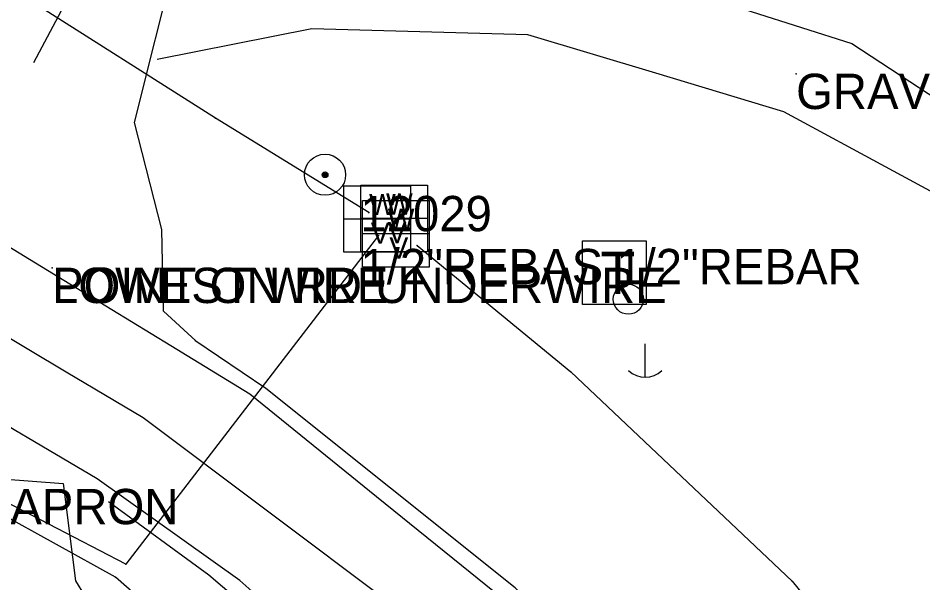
# Model space of a CAD drawing. Extents: x 1050807 to 1053552, y 395828 to 398415.
# Drawn here: x 1051909.5 to 1052037.5, y 397988.8 to 398068.8 of the extents above; entities that cross this region are included whole.
import ezdxf

# ---------------------------------------------------------------- set-up
doc = ezdxf.new("R2010")
doc.units = 0
for name, color, linetype in [('S_EDGE_PAVEMENT', 7, 'Continuous'), ('S_ELECTRIC_UTILITIES_ANNOT', 7, 'Continuous'), ('S_GRAVEL_ROAD', 7, 'Continuous'), ('S_IRON_PIN', 7, 'Continuous'), ('S_IRON_PIN_ANNOT', 7, 'Continuous'), ('S_MSC_PT_SYM', 7, 'Continuous'), ('S_PAVEMENT_CROWN', 7, 'Continuous'), ('S_SHOULDER', 7, 'Continuous'), ('S_SURVEY_TEXT_ANNOT', 7, 'Continuous'), ('S_TELEPHONE_UTILITIES', 7, 'Continuous'), ('S_UTILITY_POLE', 7, 'Continuous'), ('S_UTL_PT_SYM', 7, 'Continuous'), ('S_WATER_UTILITIES', 7, 'Continuous')]:
    doc.layers.add(name, color=color, linetype=linetype)

msp = doc.modelspace()

# ---------------------------------------------------------------- linework, layer by layer
at = {"layer": 'S_EDGE_PAVEMENT'}
for points in [[(1051934.63, 398023.1), (1051930.06, 398027.26), (1051929.8, 398038.82), (1051925.96, 398053.99), (1051931.83, 398077.54), (1051938.69, 398100.99), (1051941.54, 398122.27), (1051942, 398134.91), (1051942.46, 398147.55), (1051942.93, 398160.19), (1051943.39, 398172.83), (1051943.59, 398197.73), (1051943.79, 398222.64), (1051944.04, 398235.63), (1051944.3, 398248.63), (1051944.55, 398261.62), (1051944.81, 398274.62), (1051944.95, 398287.8), (1051945.09, 398300.98), (1051945.24, 398314.17), (1051945.38, 398327.35), (1051945.7, 398344.1), (1051946.02, 398360.85)], [(1052043.7, 397907.48), (1052036.23, 397917.81), (1052028.77, 397928.15), (1052021.31, 397938.48), (1052013.84, 397948.81), (1052004.91, 397958.24), (1051995.98, 397967.66), (1051987.04, 397977.09), (1051978.11, 397986.52), (1051960.19, 398001.02), (1051942.28, 398015.53), (1051931.11, 398022.36), (1051919.95, 398029.19), (1051908.79, 398036.02), (1051897.62, 398042.85), (1051877.43, 398052.09), (1051857.24, 398061.33), (1051844.58, 398065.54), (1051831.93, 398069.76)], [(1052038.69, 397873.19), (1052032.04, 397883.85), (1052025.39, 397894.51), (1052018.74, 397905.17), (1052012.09, 397915.83), (1052004.02, 397925.46), (1051995.95, 397935.08), (1051987.88, 397944.7), (1051979.81, 397954.32), (1051970.07, 397963.03), (1051960.33, 397971.74), (1051950.59, 397980.46), (1051940.85, 397989.17), (1051920.67, 398003.53), (1051900.02, 398015.7), (1051879.38, 398027.86), (1051867.4, 398032.67), (1051855.43, 398037.49), (1051843.45, 398042.3), (1051831.48, 398047.11), (1051807.63, 398052.86)]]:
    msp.add_lwpolyline(points, dxfattribs=at)
at = {"layer": 'S_GRAVEL_ROAD'}
for points in [[(1051941.6, 398111.76), (1051957.6, 398097.06), (1051970.21, 398085.36), (1051984.67, 398078.88), (1052006.03, 398072.02), (1052027.38, 398065.17), (1052046.41, 398052.69), (1052065.44, 398040.21), (1052080.08, 398025.28), (1052094.72, 398010.35), (1052105.27, 397991.93), (1052108.07, 397979.7), (1052110.87, 397967.48), (1052113.67, 397955.25), (1052116.48, 397943.02), (1052122.03, 397920.87), (1052127.57, 397898.72), (1052130.86, 397881.88), (1052134.15, 397865.05), (1052139.91, 397846.05), (1052147.47, 397834.83)], [(1052123.52, 397838.53), (1052126.37, 397842.85), (1052127.19, 397846.52), (1052118.6, 397865.94), (1052112.52, 397878.14), (1052106.44, 397890.34), (1052105.1, 397906.73), (1052103.75, 397923.13), (1052099.75, 397943.42), (1052095.74, 397963.72), (1052086.81, 397984.21), (1052077.87, 398004.7), (1052063.35, 398021.7), (1052048.82, 398038.69), (1052033.31, 398047.09), (1052017.79, 398055.49), (1051999.69, 398060.95), (1051981.6, 398066.41), (1051966.31, 398066.83), (1051951.02, 398067.25), (1051929.14, 398062.88)], [(1051907.2, 398003.55), (1051915.88, 398002.91), (1051917.6, 397989.1), (1051925.25, 397976.64), (1051940.24, 397961.7), (1051955.22, 397946.76), (1051966.38, 397933.09), (1051977.54, 397919.42), (1051982.83, 397903.76), (1051988.12, 397888.11), (1051995.11, 397874.29), (1052002.09, 397860.47), (1052012.08, 397846.73), (1052024.66, 397838)]]:
    msp.add_lwpolyline(points, dxfattribs=at)
at = {"layer": 'S_IRON_PIN'}
for radius in [2.91, 0.411, 0.262, 0.212, 0.145, 0.0822, 0.0581]:
    msp.add_circle((1051952.9, 398046.59), radius, dxfattribs=at)
at = {"layer": 'S_MSC_PT_SYM'}
for points in [[(1052019.52, 398060.89), (1052019.52, 398060.94), (1052019.52, 398060.89), (1052019.47, 398060.89), (1052019.52, 398060.89), (1052019.52, 398060.84), (1052019.52, 398060.89), (1052019.57, 398060.89)], [(1051914.29, 398033.43), (1051914.29, 398033.48), (1051914.29, 398033.43), (1051914.24, 398033.43), (1051914.29, 398033.43), (1051914.29, 398033.38), (1051914.29, 398033.43), (1051914.34, 398033.43)]]:
    msp.add_lwpolyline(points, dxfattribs=at)
at = {"layer": 'S_PAVEMENT_CROWN'}
for points in [[(1051911.73, 398062.49), (1051922.6, 398083.01), (1051926.16, 398095.8), (1051929.71, 398108.59), (1051932.19, 398128.36), (1051932.65, 398140.95), (1051933.12, 398153.54), (1051933.58, 398166.13), (1051934.04, 398178.71), (1051934.3, 398191.33), (1051934.55, 398203.94), (1051934.81, 398216.55), (1051935.06, 398229.16), (1051935.51, 398253.78), (1051935.96, 398278.4), (1051936.1, 398291.5), (1051936.24, 398304.61), (1051936.39, 398317.72), (1051936.53, 398330.82), (1051937.06, 398346.12), (1051937.6, 398361.41)], [(1052041.36, 397889.37), (1052035.08, 397900.29), (1052028.8, 397911.2), (1052020.99, 397921.23), (1052013.18, 397931.25), (1052005.37, 397941.28), (1051997.56, 397951.3), (1051979.95, 397968.52), (1051962.34, 397985.74), (1051944.75, 397998.96), (1051927.16, 398012.19), (1051916.3, 398018.66), (1051905.43, 398025.13), (1051894.57, 398031.6), (1051883.71, 398038.07), (1051871.84, 398042.85), (1051859.97, 398047.63), (1051848.1, 398052.42), (1051836.23, 398057.2), (1051823.74, 398060.25), (1051811.24, 398063.31)]]:
    msp.add_lwpolyline(points, dxfattribs=at)
at = {"layer": 'S_SHOULDER'}
for points in [[(1052069.97, 397864.61), (1052063.87, 397875.65), (1052057.77, 397886.69), (1052051.67, 397897.73), (1052045.57, 397908.78), (1052038.12, 397919.18), (1052030.67, 397929.57), (1052023.22, 397939.97), (1052015.78, 397950.37), (1052006.78, 397959.81), (1051997.77, 397969.24), (1051988.77, 397978.67), (1051979.77, 397988.1), (1051962.15, 398002.23), (1051944.53, 398016.35), (1051934.5, 398023.11)], [(1052050.55, 397842.58), (1052039.7, 397864.61), (1052028.85, 397886.64), (1052021.35, 397897.42), (1052013.86, 397908.2), (1052006.37, 397918.98), (1051998.87, 397929.76), (1051981.88, 397947.71), (1051964.88, 397965.66), (1051950.67, 397977.79), (1051936.46, 397989.93), (1051922.29, 398000.29)]]:
    msp.add_lwpolyline(points, dxfattribs=at)
at = {"layer": 'S_TELEPHONE_UTILITIES'}
msp.add_lwpolyline([(1051989.3, 398028.22), (1051989.3, 398037.22), (1051998.3, 398037.22), (1051998.3, 398028.22)], close=True, dxfattribs=at)
at = {"layer": 'S_UTILITY_POLE'}
for p, q in [((1051995.68, 398031.11), (1051995.68, 398033.22)), ((1051998.12, 398022.64), (1051998.12, 398017.91))]:
    msp.add_line(p, q, dxfattribs=at)
msp.add_circle((1051995.8, 398028.97), 2.13, dxfattribs=at)
msp.add_arc((1051998.18, 398021.33), 3.41, 226.3972, 313.6028, dxfattribs=at)
at = {"layer": 'S_UTL_PT_SYM'}
for points in [[(1051937.42, 398054.58), (1051937.42, 398054.63), (1051937.42, 398054.58), (1051937.37, 398054.58), (1051937.42, 398054.58), (1051937.42, 398054.53), (1051937.42, 398054.58), (1051937.47, 398054.58)], [(1051959.07, 398041.23), (1051959.07, 398041.28), (1051959.07, 398041.23), (1051959.02, 398041.23), (1051959.07, 398041.23), (1051959.07, 398041.18), (1051959.07, 398041.23), (1051959.12, 398041.23)], [(1051960.46, 398037.97), (1051960.46, 398038.02), (1051960.46, 398037.97), (1051960.41, 398037.97), (1051960.46, 398037.97), (1051960.46, 398037.92), (1051960.46, 398037.97), (1051960.51, 398037.97)], [(1051965.92, 398036.58), (1051965.92, 398036.63), (1051965.92, 398036.58), (1051965.87, 398036.58), (1051965.92, 398036.58), (1051965.92, 398036.53), (1051965.92, 398036.58), (1051965.97, 398036.58)], [(1051914.29, 398033.43), (1051914.29, 398033.48), (1051914.29, 398033.43), (1051914.24, 398033.43), (1051914.29, 398033.43), (1051914.29, 398033.38), (1051914.29, 398033.43), (1051914.34, 398033.43)], [(1051987.66, 398018.71), (1051987.66, 398018.76), (1051987.66, 398018.71), (1051987.61, 398018.71), (1051987.66, 398018.71), (1051987.66, 398018.66), (1051987.66, 398018.71), (1051987.71, 398018.71)], [(1051924.71, 397991.46), (1051924.71, 397991.51), (1051924.71, 397991.46), (1051924.66, 397991.46), (1051924.71, 397991.46), (1051924.71, 397991.41), (1051924.71, 397991.46), (1051924.76, 397991.46)], [(1051923.28, 397989.65), (1051923.28, 397989.7), (1051923.28, 397989.65), (1051923.23, 397989.65), (1051923.28, 397989.65), (1051923.28, 397989.6), (1051923.28, 397989.65), (1051923.33, 397989.65)], [(1052018.98, 397989.06), (1052018.98, 397989.11), (1052018.98, 397989.06), (1052018.93, 397989.06), (1052018.98, 397989.06), (1052018.98, 397989.01), (1052018.98, 397989.06), (1052019.03, 397989.06)]]:
    msp.add_lwpolyline(points, dxfattribs=at)
at = {"layer": 'S_WATER_UTILITIES'}
for p, q in [((1051937.42, 398054.58), (1051898.42, 398079.37)), ((1051959.07, 398041.23), (1051937.42, 398054.58)), ((1051955.57, 398045.03), (1051964.99, 398045.03)), ((1051955.57, 398035.61), (1051955.57, 398045.03)), ((1051957.96, 398045.12), (1051967.38, 398045.12)), ((1051957.96, 398035.7), (1051957.96, 398045.12)), ((1051964.99, 398045.03), (1051964.99, 398035.61)), ((1051967.38, 398045.12), (1051967.38, 398035.7)), ((1051958.21, 398042.94), (1051967.63, 398042.94)), ((1051958.21, 398033.53), (1051958.21, 398042.94)), ((1051967.63, 398042.94), (1051967.63, 398033.53)), ((1051955.57, 398040.34), (1051964.99, 398040.34)), ((1051957.96, 398040.43), (1051967.38, 398040.43)), ((1051958.21, 398038.25), (1051967.63, 398038.25)), ((1051960.46, 398037.97), (1051924.71, 397991.46)), ((1051964.99, 398035.61), (1051955.57, 398035.61)), ((1051967.38, 398035.7), (1051957.96, 398035.7)), ((1051965.92, 398036.58), (1051987.66, 398018.71)), ((1051967.63, 398033.53), (1051958.21, 398033.53)), ((1051924.71, 397991.46), (1051862.03, 398024.03)), ((1051923.28, 397989.65), (1051871.96, 398018.02)), ((1051987.66, 398018.71), (1052018.98, 397989.06)), ((1051964.28, 397953.57), (1051923.28, 397989.65)), ((1052018.98, 397989.06), (1052053.44, 397946.43))]:
    msp.add_line(p, q, dxfattribs=at)

# ---------------------------------------------------------------- texts
at = {"layer": 'S_ELECTRIC_UTILITIES_ANNOT'}
msp.add_text('LOWEST WIRE', height=5, dxfattribs=at).set_placement((1051914.29, 398028.43))
at = {"layer": 'S_IRON_PIN_ANNOT'}
for s, p in [('12029', (1051957.9, 398038.59)), ('1/2"REBAS 1/2"REBAR', (1051957.9, 398031.09))]:
    msp.add_text(s, height=5, dxfattribs=at).set_placement(p)
at = {"layer": 'S_SURVEY_TEXT_ANNOT'}
for s, p in [('GRAVEL ROAD NO NAME', (1052019.52, 398055.89)), ('POINT ON RD UNDERWIRE', (1051914.29, 398028.43)), ('CONC APRON', (1051886.84, 397997.12))]:
    msp.add_text(s, height=5, dxfattribs=at).set_placement(p)
at = {"layer": 'S_TELEPHONE_UTILITIES'}
msp.add_text('T', height=6, dxfattribs=at).set_placement((1051991.86, 398029.72))
at = {"layer": 'S_WATER_UTILITIES'}
for s, p in [('W', (1051959.12, 398040.87)), ('W', (1051961.52, 398040.96)), ('W', (1051961.76, 398038.78)), ('V', (1051959.36, 398036.81)), ('V', (1051961.75, 398036.9)), ('V', (1051962, 398034.72))]:
    msp.add_text(s, height=3, dxfattribs=at).set_placement(p)

doc.saveas('drawing.dxf')
